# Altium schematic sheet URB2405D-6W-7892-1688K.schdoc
size 277 x 190 mm; Device: default297x210; Symbol: default297x210; Name: default297x210; Date: 2026.03.04; Rev: V1.0; Size: "A4"; Id: /; File: URB2405D-6W-7892-1688K; Sheet: /
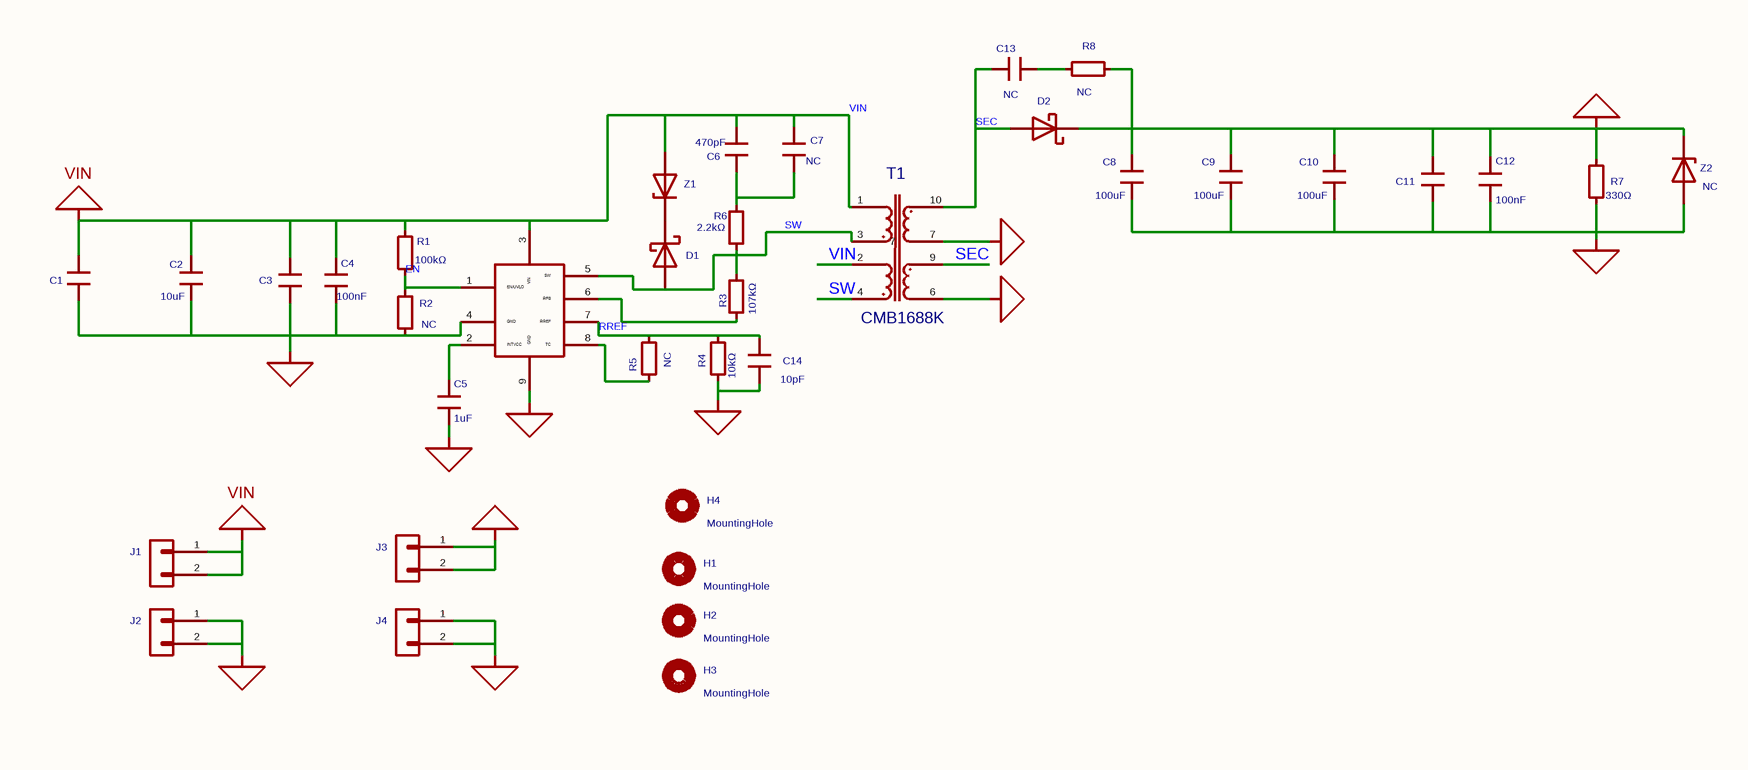
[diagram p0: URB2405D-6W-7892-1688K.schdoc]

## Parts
C1  MY_C  [MYLibrary:C1206]  (value not drawn)
C2  10uF  [MYLibrary:C1206]
C3  MY_C  [MYLibrary:C0805]  (value not drawn)
C4  100nF  [MYLibrary:C0603]
C5  1uF  [MYLibrary:C0603]
C6  470pF  [MYLibrary:C0603]
C7  value NC  [MYLibrary:C0603]  (hidden comment: My_library_C)
C8  100uF  [MYLibrary:C1206]
C9  100uF  [MYLibrary:C1206]
C10  100uF  [MYLibrary:C1206]
C11  MY_C  [MYLibrary:C0805]  (value not drawn)
C12  100nF  [MYLibrary:C0603]
C13  value NC  [MYLibrary:C0603]  (hidden comment: My_library_C)
C14  10pF  [MYLibrary:C0603]
D1  DSS210  [Diode_SMD:D_SOD-123]  (value not drawn)
D2  SS1060  [Diode_SMD:D_SMA-SMB_Universal_Handsoldering]  (value not drawn)
H1  value MountingHole  [MountingHole:MountingHole_3.2mm_M3_DIN965]  (hidden comment: Mechanical_MountingHole)
H2  value MountingHole  [MountingHole:MountingHole_3.2mm_M3_DIN965]  (hidden comment: Mechanical_MountingHole)
H3  value MountingHole  [MountingHole:MountingHole_3.2mm_M3_DIN965]  (hidden comment: Mechanical_MountingHole)
H4  value MountingHole  [MountingHole:MountingHole_3.2mm_M3_DIN965]  (hidden comment: Mechanical_MountingHole)
J1  HX PZ2.54-1x2P ZZ  [Connector_PinHeader_2.54mm:PinHeader_1x02_P2.54mm_Vertical]  (value not drawn)
J2  HX PZ2.54-1x2P ZZ  [Connector_PinHeader_2.54mm:PinHeader_1x02_P2.54mm_Vertical]  (value not drawn)
J3  HX PZ2.54-1x2P ZZ  [Connector_PinHeader_2.54mm:PinHeader_1x02_P2.54mm_Vertical]  (value not drawn)
J4  HX PZ2.54-1x2P ZZ  [Connector_PinHeader_2.54mm:PinHeader_1x02_P2.54mm_Vertical]  (value not drawn)
R1  100kΩ  [MYLibrary:R0603]
R2  value NC  [MYLibrary:R0603]  (hidden comment: Device_R_Small)
R3  107kΩ  [MYLibrary:R0603]
R4  10kΩ  [MYLibrary:R0603]
R5  value NC  [MYLibrary:R0603]  (hidden comment: Device_R_Small)
R6  2.2kΩ  [MYLibrary:R1206]
R7  330Ω  [MYLibrary:R0603]
R8  value NC  [MYLibrary:R0603]  (hidden comment: Device_R_Small)
T1  (no value)  [CMB1688K]
U1  CMP7892  [CMP7892]  (value not drawn)
Z1  1SMA5930A  [Diode_SMD:D_SMA]  (value not drawn)
Z2  value NC  [Diode_SMD:D_SMA]  (hidden comment: Diode_BZV55C75)

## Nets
GND1: C1.2 C2.2 C3.2 C4.1 C5.1 C14.1 J2.1(Pin_1) J2.2(Pin_2) R2.2 R4.2 U1.4(GND) U1.9(GND)
GND2: C8.2 C9.2 C10.2 C11.2 C12.1 J4.1(Pin_1) J4.2(Pin_2) R7.1 T1.6 T1.7 Z2.2(A)
VIN: C1.1 C2.1 C3.1 C4.2 C6.2 C7.2 J1.1(Pin_1) J1.2(Pin_2) R1.1 T1.1 T1.2 U1.3(VIN) Z1.2(A)
VOUT: C8.1 C9.1 C10.1 C11.1 C12.2 D2.1(K) J3.1(Pin_1) J3.2(Pin_2) R7.2 R8.1 Z2.1(K)
EN: R1.2 R2.1 U1.1(EN/UVLO)
RREF: C14.2 R4.1 R5.2 U1.7(RREF)
SEC: C13.2 D2.2(A) T1.9 T1.10
SW: D1.2(A) R3.2 R6.1 T1.3 T1.4 U1.5(SW)
NetC5_2: C5.2 U1.2(INTVCC)
NetC6_1: C6.1 C7.1 R6.2
NetC13_1: C13.1 R8.2
NetD1_1: D1.1(K) Z1.1(K)
NetR3_1: R3.1 U1.6(RFB)
NetR5_1: R5.1 U1.8(TC)

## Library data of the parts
C1 = MY_C: GRM31CR61H106KA12L; Value: 10uF/50V; Add into BOM: no; ki_keywords: cap capacitor; ki_fp_filters: C_*; UniqueId: 5fb4f22ffcb6a001; Attribute1: C2
C2 = CC1206KKX5R9BB106: 容值:10uF;精度:±10%;额定电压:50V;温度系数:X5R;; Manufacturer: YAGEO(国巨); Symbol: MY_C; Add into BOM: yes; 3D Model: e4be705b945545a48e666415e3682bd8; 3D Model Transform: 125.984,62.992,0,0,0,0,0,0,0; Tolerance: ±10%; Voltage Rating: 50V; Temperature Coefficient: X5R; ki_keywords: cap capacitor; ki_fp_filters: C_*; UniqueId: 21d50210554cb61f; ModelName: C1206_L3.2-W1.6-H1.3
C3 = MY_C: 0805; Value: 1uF/50V; Add into BOM: no; ki_keywords: cap capacitor; ki_fp_filters: C_*; UniqueId: ec64484c8c07847f; Attribute1: C3
C4 = CC0603KRX7R9BB104: 容值:100nF;精度:±10%;额定电压:50V;温度系数:X7R;; Manufacturer: YAGEO(国巨); Symbol: MY_C; Add into BOM: yes; 3D Model: ac125912035d415993ca9572d50418b1; 3D Model Transform: 62.992,31.496,0,0,0,0,0,0,0; Tolerance: ±10%; Voltage Rating: 50V; Temperature Coefficient: X7R; ki_keywords: cap capacitor; ki_fp_filters: C_*; UniqueId: 623e2bb2442f04df; ModelName: C0603_L1.6-W0.8-H0.8
C5 = CC0603KRX7R9BB105: 容值:1uF;精度:±10%;额定电压:50V;温度系数:X7R;; Manufacturer: YAGEO(国巨); Symbol: MY_C; Add into BOM: yes; 3D Model: ac125912035d415993ca9572d50418b1; 3D Model Transform: 62.992,31.496,0,0,0,0,0,0,0; Tolerance: ±10%; Voltage Rating: 50V; Temperature Coefficient: X7R; ki_keywords: cap capacitor; ki_fp_filters: C_*; ModelName: C0603_L1.6-W0.8-H0.8
C6 = CC0603KRX7R9BB471: 容值:470pF;精度:±10%;额定电压:50V;材质(温度系数):X7R;; Manufacturer: YAGEO(国巨); Symbol: My_library_C; Add into BOM: yes; 3D Model: ac125912035d415993ca9572d50418b1; 3D Model Transform: 62.992,31.496,0,0,0,0,0,0,0; Tolerance: ±10%; Voltage Rated: 50V; Temperature Coefficient: X7R; ki_keywords: cap capacitor; ki_fp_filters: C_*; ModelName: C0603_L1.6-W0.8-H0.8
C7 = My_library_C: Add into BOM: no; ki_keywords: cap capacitor; ki_fp_filters: C_*; Attribute1: C4
C8 = GRM31CR61A107MEA8L: 容值:100uF;精度:±20%;额定电压:10V;温度系数:X5R;; Manufacturer: muRata(村田); Symbol: MY_C; Add into BOM: yes; 3D Model: e4be705b945545a48e666415e3682bd8; 3D Model Transform: 125.984,62.992,0,0,0,0,0,0,0; Tolerance: ±20%; Voltage Rating: 10V; Temperature Coefficient: X5R; ki_keywords: cap capacitor; ki_fp_filters: C_*; UniqueId: 878ab3ab0cce2757; ModelName: C1206_L3.2-W1.6-H1.3
C9 = GRM31CR61A107MEA8L: 容值:100uF;精度:±20%;额定电压:10V;温度系数:X5R;; Manufacturer: muRata(村田); Symbol: MY_C; Add into BOM: yes; 3D Model: e4be705b945545a48e666415e3682bd8; 3D Model Transform: 125.984,62.992,0,0,0,0,0,0,0; Tolerance: ±20%; Voltage Rating: 10V; Temperature Coefficient: X5R; ki_keywords: cap capacitor; ki_fp_filters: C_*; UniqueId: 60e6893b044e2f17; ModelName: C1206_L3.2-W1.6-H1.3
C10 = GRM31CR61A107MEA8L: 容值:100uF;精度:±20%;额定电压:10V;温度系数:X5R;; Manufacturer: muRata(村田); Symbol: MY_C; Add into BOM: yes; 3D Model: e4be705b945545a48e666415e3682bd8; 3D Model Transform: 125.984,62.992,0,0,0,0,0,0,0; Tolerance: ±20%; Voltage Rating: 10V; Temperature Coefficient: X5R; ki_keywords: cap capacitor; ki_fp_filters: C_*; UniqueId: c1764753ee6525b4; ModelName: C1206_L3.2-W1.6-H1.3
C11 = MY_C: 0805; Value: 1uF/50V; Add into BOM: no; ki_keywords: cap capacitor; ki_fp_filters: C_*; UniqueId: b49c3108c5288e9f; Attribute1: C3
C12 = CC0603KRX7R9BB104: 容值:100nF;精度:±10%;额定电压:50V;温度系数:X7R;; Manufacturer: YAGEO(国巨); Symbol: MY_C; Add into BOM: yes; 3D Model: ac125912035d415993ca9572d50418b1; 3D Model Transform: 62.992,31.496,0,0,0,0,0,0,0; Tolerance: ±10%; Voltage Rating: 50V; Temperature Coefficient: X7R; ki_keywords: cap capacitor; ki_fp_filters: C_*; UniqueId: 4eba2014d94c20ef; ModelName: C0603_L1.6-W0.8-H0.8
C13 = My_library_C: Add into BOM: no; ki_keywords: cap capacitor; ki_fp_filters: C_*; UniqueId: 8d11a04c32f33369; Attribute1: C4
C14 = CC0603JRNPO9BN100: 容值:10pF;精度:±5%;额定电压:50V;温度系数:NP0;; Manufacturer: YAGEO(国巨); Symbol: My_library_C; Add into BOM: yes; 3D Model: ac125912035d415993ca9572d50418b1; 3D Model Transform: 62.992,31.496,0,0,0,0,0,0,0; Tolerance: ±5%; Voltage Rating: 50V; Temperature Coefficient: NP0; ki_keywords: cap capacitor; ki_fp_filters: C_*; UniqueId: c9f451b8b2c5f180; ModelName: C0603_L1.6-W0.8-H0.8
D1 = DSS210: 二极管配置:独立式;正向压降(Vf):850mV@2A;直流反向耐压(Vr):100V;整流电流:2A;; Manufacturer: CJ(江苏长电/长晶); Symbol: My library_DSS210; Add into BOM: yes; 3D Model: 125b22121bda4d3999c0a2016797619b; 3D Model Transform: 145.669,70.866,0,0,0,0,0,0,0; Diode Configuration: 独立式; Voltage - DC Reverse(Vr): 100V; Current - Rectified: 2A; Reverse Leakage Current (Ir): 100uA@100V; Operating Junction Temperature Range: -55℃~+150℃; Non-Repetitive Peak Forward Surge Current: 40A; ki_keywords: diode; ki_fp_filters: TO-???* *_Diode_* *SingleDiode* D_*; UniqueId: de80be6c74b1ca94; ModelName: SOD-123_L2.8-W1.8-H1.4-LS3.7
D2 = SS1060_C2922189: 二极管配置:独立式;正向压降(Vf):700mV@10A;直流反向耐压(Vr):60V;整流电流:10A;; Manufacturer: GOODWORK(固得沃克); Symbol: My library_DSS210; Add into BOM: yes; 3D Model: 12d69a27526645cbb79f2d2a354dc150; 3D Model Transform: 307.086,232.283,0,0,0,0,0,0,0; Diode Configuration: 独立式; Voltage - DC Reverse(Vr): 60V; Current - Rectified: 10A; Reverse Leakage Current (Ir): 100nA; Operating Junction Temperature Range: -55℃~+175℃; Value: DSS210; ki_keywords: diode; ki_fp_filters: TO-???* *_Diode_* *SingleDiode* D_*; UniqueId: gge1; ModelName: SMC_L6.8-W5.9-LS7.8-RD
H1-H4 = Mechanical_MountingHole: ki_fp_filters: MountingHole*; Attribute1: H1; AddInBom: yes
J1-J4 = HX PZ2.54-1x2P ZZ: 插针结构:1x2P;间距:2.54mm;行距:-;圆针/方针:方针;安装方式:直插;排数:单排;总PIN位数:2P;额定电流:3A;额定电压:1kV;配合针长度:6mm;塑高:2.5mm;端接针长度:3mm;触头材质:黄铜;触头镀层:金;工作温度:-40℃~+105℃;颜色:黑色;; Manufacturer: hanxia(韩下); Symbol: Connector_Generic_Conn_01x02; Add into BOM: yes; 3D Model: c7a9f3c3e6e34627af2bf939e464cb35; 3D Model Transform: 200,100,0,0,0,0,0,0,-118.11; Pin Structure: 1x2P; Pitch: 2.54mm; Circluar Pins/Square Pins: 方针; Current Rating: 3A; Voltage Rating (Max): 1kV; ki_keywords: connector; ki_fp_filters: Connector*:*_1x??_*; ModelName: HDR-TH_2P-P2.54-M-LI-1X2P
R1 = RC0603FR-07100KL: 电阻类型:厚膜电阻;阻值:100kΩ;精度:±1%;功率:100mW;最大工作电压:75V;温度系数:±100ppm/℃;; Manufacturer: YAGEO(国巨); Symbol: Device_R_Small; Add into BOM: yes; 3D Model: fc143cca1e79419f9cd78b61e9279f08; 3D Model Transform: 31.8897,63.7794,0,90,0,0,0,0,0; Tolerance: ±1%; Power(Watts): 100mW; Overload Voltage (Max): 75V; ki_keywords: R resistor; ki_fp_filters: R_*; UniqueId: 4e166b190d4de1c3; ModelName: R0603
R2 = Device_R_Small: Resistor, small symbol; Add into BOM: no; ki_keywords: R resistor; ki_fp_filters: R_*; UniqueId: 06442d24ab060343; Attribute1: R8
R3 = RC0603FR-07107KL: 电阻类型:厚膜电阻;阻值:107kΩ;精度:±1%;功率:100mW;最大工作电压:75V;温度系数:±100ppm/℃;; Manufacturer: YAGEO(国巨); Symbol: Device_R_Small; Add into BOM: yes; 3D Model: fc143cca1e79419f9cd78b61e9279f08; 3D Model Transform: 31.8897,63.7794,0,90,0,0,0,0,0; Tolerance: ±1%; Power(Watts): 100mW; Overload Voltage (Max): 75V; ki_keywords: R resistor; ki_fp_filters: R_*; ModelName: R0603
R4 = RC0603FR-0710KL: 电阻类型:厚膜电阻;阻值:10kΩ;精度:±1%;功率:100mW;最大工作电压:75V;温度系数:±100ppm/℃;; Manufacturer: YAGEO(国巨); Symbol: Device_R_Small; Add into BOM: yes; 3D Model: fc143cca1e79419f9cd78b61e9279f08; 3D Model Transform: 31.8897,63.7794,0,90,0,0,0,0,0; Tolerance: ±1%; Power(Watts): 100mW; Overload Voltage (Max): 75V; ki_keywords: R resistor; ki_fp_filters: R_*; UniqueId: 49359f7360e76581; ModelName: R0603
R5 = Device_R_Small: Resistor, small symbol; Add into BOM: no; ki_keywords: R resistor; ki_fp_filters: R_*; UniqueId: 96bd3269827a783e; Attribute1: R8
R6 = RC1206FR-072K2L: 电阻类型:厚膜电阻;阻值:2.2kΩ;精度:±1%;功率:250mW;工作电压:200V;温度系数:±100ppm/℃;; Manufacturer: YAGEO(国巨); Symbol: Device_R_Small; Add into BOM: yes; 3D Model: 89a1f13db2384da588040e0b3c55bf66; 3D Model Transform: 125.984,62.992,0,0,0,0,0,0,0; Tolerance: ±1%; Power(Watts): 250mW; Voltage-Supply(Max): 200V; ki_keywords: R resistor; ki_fp_filters: R_*; ModelName: R1206_L3.2-W1.6-H0.6
R7 = RC0603FR-07330RL: 电阻类型:厚膜电阻;阻值:330Ω;精度:±1%;功率:100mW;最大工作电压:75V;温度系数:±100ppm/℃;; Manufacturer: YAGEO(国巨); Symbol: Device_R_Small; Add into BOM: yes; 3D Model: fc143cca1e79419f9cd78b61e9279f08; 3D Model Transform: 31.8897,63.7794,0,90,0,0,0,0,0; Tolerance: ±1%; Power(Watts): 100mW; Overload Voltage (Max): 75V; ki_keywords: R resistor; ki_fp_filters: R_*; UniqueId: 01f5c70ff2630ee7; ModelName: R0603
R8 = Device_R_Small: Resistor, small symbol; Add into BOM: no; ki_keywords: R resistor; ki_fp_filters: R_*; UniqueId: f0665cc51e401020; Attribute1: R8
T1 = CMB1688K: AddInBom: yes
U1 = CMP7892: Manufacturer: coileasy(线易); AddInBom: yes; ModelId: f43fc10339aa42ce991094e4756959b90819f05c4eef4c71ace90d822a990e87; ModelName: ESOP-8_L4.9-W3.9-P1.27-LS6.0-BL-EP3.3; ModelTransform: 192.913,236.22,0,0,0,0,0,0,0
Z1 = 1SMA5930A: 二极管配置:独立式;稳压值(标称值):16V;稳压值(范围):14.4V~17.6V;耗散功率(Pd):1.5W;; Manufacturer: LGE(鲁光); Symbol: Diode_BZV55C75; Add into BOM: yes; 3D Model: e3551acb3c5a4975a5e9d36087fe1fa2; 3D Model Transform: 185.039,102.362,0,0,0,0,0,0,0; Diode Configuration: 独立式; Zener Voltage(Nom): 16V; Reverse Leakage Current (Ir): 1uA@12.2V; Pd - Power Dissipation: 1.5W; Impedance(Zzt): 10Ω; Impedance(Zzk): 600Ω; Operating Junction Temperature Range: -55℃~+150℃; ki_keywords: zener diode; ki_fp_filters: D*MiniMELF*; Origin Footprint: Diode_SMD:D_MiniMELF; UniqueId: d022797895385730; ModelName: SMA_L4.3-W2.6-LS5.2-RD
Z2 = Diode_BZV55C75: Add into BOM: no; ki_keywords: zener diode; ki_fp_filters: D*MiniMELF*; Origin Footprint: Diode_SMD:D_MiniMELF; UniqueId: 2477e26b20e1c3a5; Attribute1: Z2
